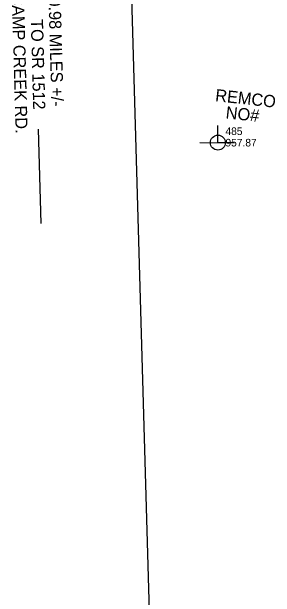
# Model space of a CAD drawing. Extents: x 1150279 to 1151282, y 654632 to 657999.
# Drawn here: x 1150579.1 to 1150665.5, y 656816.9 to 657009.2 of the extents above; entities that cross this region are included whole.
import ezdxf

# ---------------------------------------------------------------- set-up
doc = ezdxf.new("R2010")
doc.units = 0
for name, color, linetype in [('COGO Default Chain', 7, 'Continuous'), ('Exist Roads EOP Leader', 7, 'Continuous'), ('Exist Roads EOP Text', 7, 'Continuous'), ('Exist Utilities Power Joint Use Telephone CELL', 7, 'Continuous'), ('Exist Utilities Power Joint Use Telephone Cogo Elevation', 7, 'Continuous'), ('Exist Utilities Power Joint Use Telephone Cogo Number', 7, 'Continuous'), ('Exist Utilities Power Joint Use Telephone Text', 7, 'Continuous')]:
    doc.layers.add(name, color=color, linetype=linetype)

msp = doc.modelspace()

# ---------------------------------------------------------------- linework, layer by layer
at = {"layer": 'COGO Default Chain'}
msp.add_line((1150663.4, 655450.47), (1150614.76, 657145.26), dxfattribs=at)
at = {"layer": 'Exist Roads EOP Leader'}
msp.add_line((1150588.77, 656939.61), (1150587.95, 656970.64), dxfattribs=at)
at = {"layer": 'Exist Utilities Power Joint Use Telephone CELL'}
msp.add_line((1150646.7, 656966.2), (1150646.7, 656966.2), dxfattribs=at)
msp.add_lwpolyline([(1150640.76, 656966.2), (1150652.1, 656966.16), (1150646.7, 656966.18), (1150646.7, 656971.83)], dxfattribs=at)
msp.add_circle((1150646.7, 656966.21), 2.45, dxfattribs=at)

# ---------------------------------------------------------------- texts
at = {"layer": 'Exist Roads EOP Text'}
for s, p in [('CAMP CREEK RD.', (1150579.14, 657015.19)), ('0.98 MILES +/-', (1150591.18, 657013.83)), ('TO SR 1512', (1150585.37, 657006.72))]:
    msp.add_text(s, height=4, rotation=271.5458, dxfattribs=at).set_placement(p)
at = {"layer": 'Exist Utilities Power Joint Use Telephone Cogo Elevation'}
msp.add_text('957.87', height=2.5, dxfattribs=at).set_placement((1150649.2, 656964.95))
at = {"layer": 'Exist Utilities Power Joint Use Telephone Cogo Number'}
msp.add_text('485', height=2.5, dxfattribs=at).set_placement((1150649.2, 656968.7))
at = {"layer": 'Exist Utilities Power Joint Use Telephone Text'}
for s, p in [('REMCO', (1150645.7, 656979.86)), ('NO#', (1150649.13, 656974.2))]:
    msp.add_text(s, height=4, rotation=353.6867, dxfattribs=at).set_placement(p)

doc.saveas('drawing.dxf')
